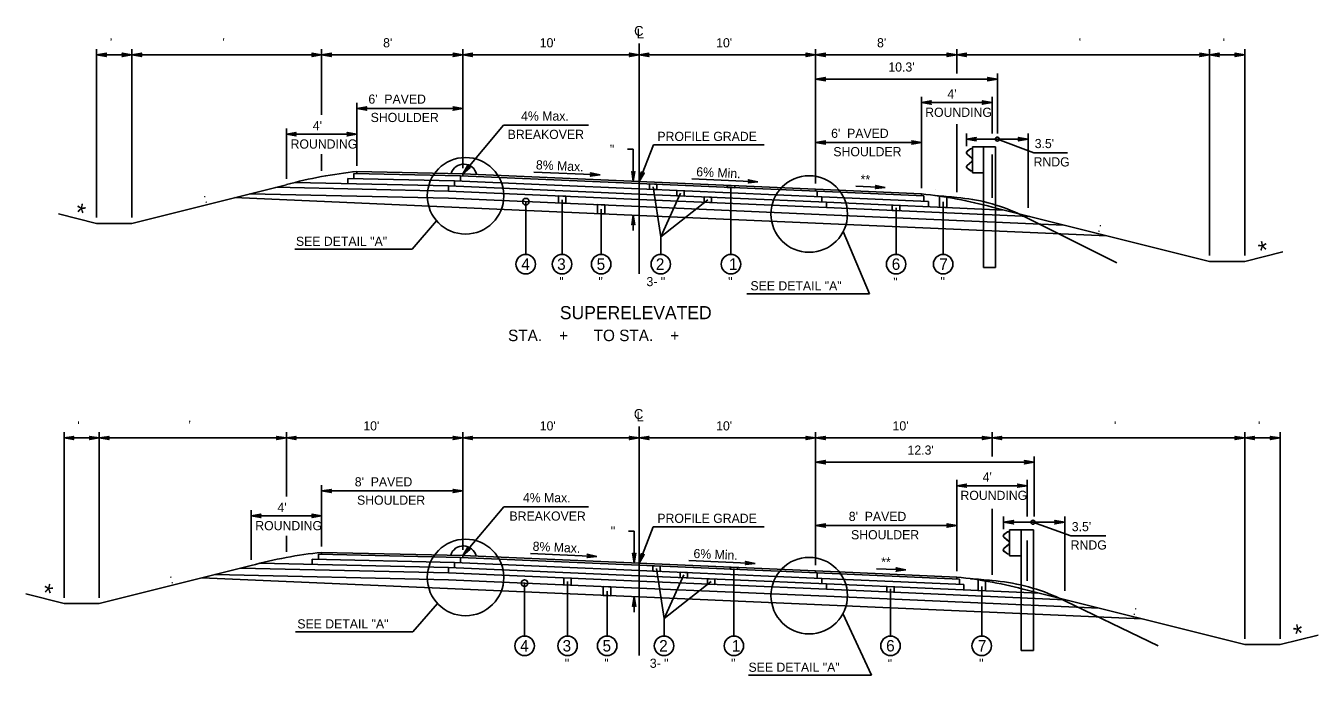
# Model space of a CAD drawing. Extents: x -592 to 1199, y -590 to 416.
# Drawn here: x 451 to 648.3, y -323.9 to -224.8 of the extents above; entities that cross this region are included whole.
import ezdxf

# ---------------------------------------------------------------- set-up
doc = ezdxf.new("R2010")
doc.units = 0
doc.layers.add('1', color=7, linetype='Continuous')
doc.layers.add('Des_ Drain_ Ftrs', color=7, linetype='Continuous')

msp = doc.modelspace()

# ---------------------------------------------------------------- linework, layer by layer
at = {"layer": '1'}
for p, q in [((461.76, -254.1), (461.76, -228.39)), ((467.15, -254.1), (467.15, -228.39)), ((496.12, -238.44), (496.12, -228.39)), ((517.68, -246.54), (517.68, -228.39)), ((544.62, -262.69), (544.62, -227.51)), ((571.56, -248.9), (571.56, -228.39)), ((593.11, -232.09), (593.11, -228.39)), ((631.7, -259.91), (631.7, -228.39)), ((637.09, -259.91), (637.09, -228.39)), ((467.15, -229.27), (461.76, -229.27)), ((496.12, -229.27), (467.15, -229.27)), ((517.68, -229.27), (496.12, -229.27)), ((544.62, -229.27), (517.68, -229.27)), ((544.62, -229.27), (571.56, -229.27)), ((571.56, -229.27), (593.11, -229.27)), ((593.11, -229.27), (631.7, -229.27)), ((631.7, -229.27), (637.09, -229.27)), ((599.31, -241.25), (599.31, -232.09)), ((571.56, -232.97), (599.31, -232.97)), ((501.51, -246.19), (501.51, -236.59)), ((587.72, -249.6), (587.72, -235.67)), ((587.72, -236.55), (598.5, -236.55)), ((598.5, -241.25), (598.5, -235.67)), ((517.68, -237.47), (501.51, -237.47)), ((490.74, -248.2), (490.74, -240.51)), ((517.67, -247.42), (523.89, -240)), ((536.86, -240), (523.89, -240)), ((593.11, -250.2), (593.11, -239.84)), ((501.51, -241.39), (490.74, -241.39)), ((571.56, -242.64), (587.72, -242.64)), ((594.62, -243.2), (594.62, -241.25)), ((594.62, -242.13), (604, -242.13)), ((599.31, -242.13), (604.87, -244.2)), ((604, -252.61), (604, -241.25)), ((496.12, -246.97), (496.12, -244.43)), ((543.72, -243.68), (542.84, -243.68)), ((543.72, -243.68), (543.72, -248.56)), ((544.63, -248.61), (546.79, -243)), ((563.71, -243), (546.79, -243)), ((594.68, -244.42), (595.41, -245.06)), ((595.21, -243.6), (594.7, -243.99)), ((594.7, -244.4), (595.43, -245.03)), ((595.23, -243.63), (594.71, -244.01)), ((595.53, -243.54), (595.21, -243.6)), ((595.53, -243.57), (595.23, -243.63)), ((595.53, -243.31), (595.53, -247.25)), ((595.53, -243.31), (597.21, -243.31)), ((597.21, -243.31), (597.21, -261.71)), ((599.04, -243.31), (597.21, -243.31)), ((598.5, -251.09), (598.5, -244.48)), ((599.04, -243.31), (599.04, -261.71)), ((604.87, -244.2), (610.02, -244.2)), ((595.41, -245.51), (594.68, -246.14)), ((595.43, -245.53), (594.7, -246.16)), ((594.7, -246.57), (595.21, -246.96)), ((594.71, -246.55), (595.23, -246.93)), ((595.5, -245.24), (595.5, -245.32)), ((595.53, -245.24), (595.53, -245.32)), ((500.13, -248.12), (516.41, -248.48)), ((500.13, -248.91), (500.13, -248.12)), ((501.06, -247.36), (517.33, -247.71)), ((501.06, -248.14), (501.06, -247.36)), ((501.51, -247.07), (517.67, -247.42)), ((501.51, -247.07), (501.51, -247.37)), ((544.62, -249.71), (516.41, -248.48)), ((516.41, -249.29), (516.41, -248.48)), ((544.62, -248.9), (517.33, -247.71)), ((517.33, -248.52), (517.33, -247.71)), ((544.62, -248.6), (517.67, -247.42)), ((517.67, -247.42), (517.67, -247.72)), ((528.53, -247.15), (538.65, -247.59)), ((571.56, -249.78), (544.62, -248.6)), ((552.65, -248.19), (562.76, -248.63)), ((595.21, -246.96), (595.53, -247.02)), ((595.23, -246.93), (595.53, -246.99)), ((595.53, -247.25), (597.21, -247.25)), ((490.74, -249.08), (467.15, -254.98)), ((485.17, -250.47), (515.49, -251.14)), ((489.14, -249.48), (515.49, -250.06)), ((492.06, -248.74), (515.49, -249.25)), ((544.62, -250.52), (515.49, -249.25)), ((515.49, -250.06), (515.49, -249.25)), ((544.62, -251.33), (515.49, -250.06)), ((571.8, -250.09), (544.62, -248.9)), ((572.5, -250.93), (544.62, -249.71)), ((573.21, -251.77), (544.62, -250.52)), ((546.74, -249.4), (547.91, -257.02)), ((550.92, -250.38), (547.91, -257.02)), ((558.63, -249.39), (558.63, -259.72)), ((587.72, -250.48), (571.56, -249.78)), ((571.56, -250.08), (571.56, -249.78)), ((588.09, -250.8), (571.8, -250.09)), ((571.8, -250.09), (571.8, -250.9)), ((582.2, -249.5), (577.7, -249.3)), ((587.72, -250.78), (587.72, -250.48)), ((589.92, -249.87), (589.92, -249.87)), ((544.62, -253.76), (482.84, -251.06)), ((544.62, -252.41), (515.49, -251.14)), ((527.29, -251.67), (527.29, -259.72)), ((532.84, -251.38), (532.84, -259.72)), ((573.21, -252.58), (544.62, -251.33)), ((573.21, -253.66), (544.62, -252.41)), ((555.1, -251.39), (547.91, -257.02)), ((588.78, -251.64), (572.5, -250.93)), ((572.5, -250.93), (572.5, -251.74)), ((573.21, -251.77), (573.21, -252.58)), ((600.33, -252.95), (573.21, -251.77)), ((604.25, -253.93), (573.21, -252.58)), ((588.09, -250.8), (588.09, -251.61)), ((588.78, -251.64), (588.78, -252.45)), ((591.04, -251.69), (591.04, -259.72)), ((594.62, -251.26), (594.62, -251.26)), ((598.5, -252.49), (631.7, -260.79)), ((455.94, -253.52), (461.76, -254.98)), ((538.81, -252.8), (538.81, -259.72)), ((543.72, -253.71), (543.72, -256.08)), ((616.02, -256.87), (544.62, -253.76)), ((609.48, -255.24), (573.21, -253.66)), ((583.85, -252.61), (583.85, -259.72)), ((602.5, -253.49), (617.55, -261.02)), ((467.15, -254.98), (461.76, -254.98)), ((509.94, -258.92), (513.68, -254.6)), ((575.76, -256.25), (579.81, -265.72)), ((547.91, -257.02), (547.91, -259.72)), ((492.01, -258.92), (509.94, -258.92)), ((642.91, -259.34), (637.09, -260.79)), ((599.04, -261.71), (597.21, -261.71)), ((631.7, -260.79), (637.09, -260.79)), ((561.03, -265.72), (579.81, -265.72)), ((544.62, -320.94), (544.62, -285.98)), ((456.78, -312.13), (456.78, -286.86)), ((462.17, -287.74), (456.78, -287.74)), ((462.17, -312.13), (462.17, -286.86)), ((490.74, -287.74), (462.17, -287.74)), ((490.74, -296.69), (490.74, -286.86)), ((517.68, -287.74), (490.74, -287.74)), ((517.68, -304.79), (517.68, -286.86)), ((544.62, -287.74), (517.68, -287.74)), ((544.62, -287.74), (571.56, -287.74)), ((571.56, -307.15), (571.56, -286.86)), ((571.56, -287.74), (598.5, -287.74)), ((598.5, -290.56), (598.5, -286.86)), ((598.5, -287.74), (637.09, -287.74)), ((637.09, -318.4), (637.09, -286.86)), ((637.09, -287.74), (642.48, -287.74)), ((642.48, -318.4), (642.48, -286.86)), ((571.56, -291.44), (604.93, -291.44)), ((604.93, -299.72), (604.93, -290.56)), ((496.12, -304.32), (496.12, -294.95)), ((517.68, -295.83), (496.12, -295.83)), ((593.11, -308.09), (593.11, -294.14)), ((593.11, -295.02), (603.89, -295.02)), ((603.89, -299.72), (603.89, -294.14)), ((485.35, -306.33), (485.35, -298.75)), ((496.12, -299.63), (485.35, -299.63)), ((517.67, -305.67), (523.96, -298.26)), ((536.89, -298.26), (523.96, -298.26)), ((598.5, -308.63), (598.5, -298.57)), ((600.23, -301.67), (600.23, -299.72)), ((609.62, -311.08), (609.62, -299.72)), ((543.86, -301.94), (542.98, -301.94)), ((543.86, -301.94), (543.86, -306.82)), ((544.63, -306.86), (546.77, -301.28)), ((563.69, -301.28), (546.77, -301.28)), ((571.56, -301.11), (593.11, -301.11)), ((600.23, -300.6), (609.62, -300.6)), ((601.18, -301.78), (601.18, -305.71)), ((601.18, -301.78), (602.93, -301.78)), ((602.93, -301.78), (602.93, -320.18)), ((604.82, -301.78), (602.93, -301.78)), ((604.75, -300.6), (610.52, -302.67)), ((604.82, -301.78), (604.82, -320.18)), ((490.74, -305.1), (490.74, -302.7)), ((600.3, -302.89), (601.06, -303.52)), ((600.85, -302.07), (600.32, -302.45)), ((600.32, -302.86), (601.08, -303.5)), ((600.87, -302.09), (600.34, -302.48)), ((601.18, -302.01), (600.85, -302.07)), ((601.18, -302.04), (600.87, -302.09)), ((601.15, -303.71), (601.15, -303.79)), ((601.18, -303.71), (601.18, -303.79)), ((603.89, -309.54), (603.89, -303.39)), ((610.52, -302.67), (615.86, -302.67)), ((495.63, -305.49), (517.33, -305.96)), ((495.63, -306.28), (495.63, -305.49)), ((496.12, -305.2), (517.67, -305.67)), ((496.12, -305.2), (496.12, -305.5)), ((544.62, -306.85), (517.67, -305.67)), ((517.67, -305.97), (517.67, -305.67)), ((528.04, -305.37), (538.15, -305.81)), ((601.06, -303.97), (600.3, -304.61)), ((601.08, -304), (600.32, -304.63)), ((600.32, -305.04), (600.85, -305.43)), ((600.34, -305.02), (600.87, -305.4)), ((600.85, -305.43), (601.18, -305.49)), ((600.87, -305.4), (601.18, -305.46)), ((601.18, -305.71), (602.93, -305.71)), ((485.35, -307.21), (462.17, -313.01)), ((483.75, -307.61), (515.49, -308.3)), ((486.67, -306.87), (515.49, -307.5)), ((494.7, -306.25), (516.41, -306.73)), ((494.7, -306.94), (494.7, -306.25)), ((544.62, -308.77), (515.49, -307.5)), ((515.49, -308.3), (515.49, -307.5)), ((544.62, -307.96), (516.41, -306.73)), ((516.41, -307.54), (516.41, -306.73)), ((544.62, -307.15), (517.33, -305.96)), ((517.33, -306.77), (517.33, -305.96)), ((571.56, -308.03), (544.62, -306.85)), ((571.8, -308.34), (544.62, -307.15)), ((547.25, -307.66), (548.41, -315.29)), ((552.21, -306.45), (562.33, -306.89)), ((559.08, -307.64), (559.08, -317.97)), ((585.34, -307.88), (580.85, -307.69)), ((544.62, -312), (477.85, -309.09)), ((479.79, -308.6), (515.49, -309.38)), ((544.62, -309.58), (515.49, -308.3)), ((544.62, -310.66), (515.49, -309.38)), ((533.68, -309.64), (533.68, -317.97)), ((572.5, -309.18), (544.62, -307.96)), ((573.21, -310.02), (544.62, -308.77)), ((573.21, -310.82), (544.62, -309.58)), ((551.43, -308.64), (548.41, -315.29)), ((555.6, -309.66), (548.41, -315.29)), ((593.11, -308.97), (571.56, -308.03)), ((571.56, -308.33), (571.56, -308.03)), ((593.51, -309.28), (571.8, -308.34)), ((571.8, -308.34), (571.8, -309.15)), ((594.2, -310.12), (572.5, -309.18)), ((572.5, -309.18), (572.5, -309.99)), ((593.11, -308.97), (593.11, -309.27)), ((593.51, -309.28), (593.51, -310.09)), ((600.23, -309.73), (600.23, -309.73)), ((450.95, -311.55), (456.78, -313.01)), ((527.12, -309.89), (527.12, -317.97)), ((539.72, -311.11), (539.72, -317.97)), ((573.21, -311.9), (544.62, -310.66)), ((573.21, -310.02), (573.21, -310.82)), ((605.72, -311.44), (573.21, -310.02)), ((609.64, -312.42), (573.21, -310.82)), ((582.99, -310.79), (582.99, -317.97)), ((594.2, -310.12), (594.2, -310.93)), ((596.93, -310.41), (596.93, -317.97)), ((603.89, -310.98), (637.09, -319.28)), ((462.17, -313.01), (456.78, -313.01)), ((510.07, -317.31), (513.81, -312.99)), ((543.86, -311.97), (543.86, -314.34)), ((621.4, -315.36), (544.62, -312)), ((614.87, -313.72), (573.21, -311.9)), ((608.24, -311.96), (623.85, -319.49)), ((548.41, -315.29), (548.41, -317.97)), ((575.74, -314.54), (580.09, -323.94)), ((492.14, -317.31), (510.07, -317.31)), ((637.09, -319.28), (642.48, -319.28)), ((648.3, -317.82), (642.48, -319.28)), ((604.82, -320.18), (602.93, -320.18)), ((561.3, -323.94), (580.09, -323.94))]:
    msp.add_line(p, q, dxfattribs=at)
for points in [[(546.17, -248.97), (547.32, -249.02), (547.32, -249.83), (546.17, -249.78)], [(550.35, -249.96), (551.49, -250.01), (551.49, -250.82), (550.35, -250.77)], [(558.06, -249.19), (559.2, -249.24), (559.2, -249.54), (558.06, -249.49)], [(532.27, -250.79), (533.41, -250.84), (533.41, -251.92), (532.27, -251.87)], [(538.24, -252.13), (539.38, -252.18), (539.38, -253.53), (538.24, -253.48)], [(554.52, -250.95), (555.67, -251), (555.67, -251.81), (554.52, -251.76)], [(583.27, -252.21), (584.42, -252.26), (584.42, -253.07), (583.27, -253.02)], [(590.47, -250.83), (591.62, -251), (591.62, -252.57), (590.47, -252.52)], [(546.68, -307.24), (547.82, -307.29), (547.82, -308.1), (546.68, -308.05)], [(558.5, -307.46), (559.65, -307.51), (559.65, -307.81), (558.5, -307.76)], [(533.11, -309.07), (534.25, -309.12), (534.25, -310.2), (533.11, -310.15)], [(550.85, -308.23), (552, -308.28), (552, -309.09), (550.85, -309.04)], [(555.03, -309.22), (556.17, -309.27), (556.17, -310.08), (555.03, -310.03)], [(596.36, -309.38), (597.5, -309.57), (597.5, -311.08), (596.36, -311.03)], [(539.14, -310.42), (540.29, -310.47), (540.29, -311.81), (539.14, -311.76)], [(582.42, -310.42), (583.57, -310.47), (583.57, -311.28), (582.42, -311.23)]]:
    msp.add_lwpolyline(points, close=True, dxfattribs=at)
for centre, radius in [((599.31, -242.13), 0.3), ((518.1, -250.78), 5.84), ((570.58, -253.56), 5.84), ((527.29, -251.67), 0.5), ((527.29, -261.21), 1.49), ((532.84, -261.21), 1.49), ((538.81, -261.21), 1.49), ((547.91, -261.21), 1.49), ((558.63, -261.21), 1.49), ((583.85, -261.21), 1.49), ((591.04, -261.21), 1.49), ((518.1, -309.03), 5.84), ((570.58, -311.8), 5.84), ((527.12, -309.89), 0.5), ((527.12, -319.46), 1.49), ((533.68, -319.46), 1.49), ((539.72, -319.46), 1.49), ((548.41, -319.46), 1.49), ((559.08, -319.46), 1.49), ((582.99, -319.46), 1.49), ((596.93, -319.46), 1.49)]:
    msp.add_circle(centre, radius, dxfattribs=at)
for centre, radius, start, end in [((594.86, -244.21), 0.278, 126.9799, 229.021), ((594.86, -244.21), 0.249, 126.9799, 229.021), ((517.83, -247.94), 2, 12.248, 163.8639), ((594.86, -246.35), 0.278, 130.979, 233.0201), ((594.86, -246.35), 0.249, 130.979, 233.0201), ((595.25, -245.24), 0.249, 0, 49.0365), ((595.25, -245.32), 0.249, 310.9635, 0), ((595.25, -245.24), 0.278, 0, 49.0365), ((595.25, -245.32), 0.278, 310.9635, 0), ((508.41, -313.9), 67.19, 95.8897, 105.2483), ((580.84, -317.32), 67.19, 74.7602, 84.1188), ((582.29, -351.7), 101.24, 83.8633, 85.6775), ((590.99, -278.33), 27.37, 65.1374, 85.5513), ((503.02, -372.04), 67.19, 95.8911, 105.2497), ((517.75, -306.21), 2, 12.9578, 163.1197), ((586.23, -375.8), 67.19, 74.7602, 84.1188)]:
    msp.add_arc(centre, radius, start, end, dxfattribs=at)
msp.add_ellipse((604.75, -300.6), major_axis=(-0.311, 0), ratio=0.964041, dxfattribs=at)
for centre, major_axis, start_param, end_param in [((600.49, -302.68), (-0.288, 0), 5.35781, 7.138763), ((600.49, -302.68), (-0.258, 0), 5.35781, 7.138763), ((600.89, -303.71), (0.258, 0), 0, 0.855848), ((600.89, -303.79), (0.258, 0), 5.427337, 6.283185), ((600.89, -303.71), (0.288, 0), 0, 0.855848), ((600.89, -303.79), (0.288, 0), 5.427337, 6.283185), ((600.49, -304.82), (-0.288, 0), 5.427608, 7.208561), ((600.49, -304.82), (-0.258, 0), 5.427608, 7.208561), ((587.28, -410.17), (105.02, 0), 1.463691, 1.495354), ((596.3, -336.79), (28.39, 0), 1.136862, 1.493152)]:
    msp.add_ellipse(centre, major_axis=major_axis, ratio=0.964041, start_param=start_param, end_param=end_param, dxfattribs=at)
at = {"layer": 'Des_ Drain_ Ftrs'}
for points in [[(461.76, -229.27), (463.25, -229.52), (462.96, -229.27), (463.25, -229.02)], [(467.15, -229.27), (465.66, -229.52), (465.96, -229.27), (465.66, -229.02)], [(467.15, -229.27), (468.64, -229.52), (468.35, -229.27), (468.64, -229.02)], [(496.12, -229.27), (494.64, -229.52), (494.93, -229.27), (494.64, -229.02)], [(496.12, -229.27), (497.61, -229.52), (497.32, -229.27), (497.61, -229.02)], [(517.68, -229.27), (516.19, -229.52), (516.48, -229.27), (516.19, -229.02)], [(517.68, -229.27), (519.16, -229.52), (518.87, -229.27), (519.16, -229.02)], [(544.62, -229.27), (543.13, -229.52), (543.42, -229.27), (543.13, -229.02)], [(544.62, -229.27), (546.11, -229.52), (545.81, -229.27), (546.11, -229.02)], [(571.56, -229.27), (570.07, -229.52), (570.37, -229.27), (570.07, -229.02)], [(571.56, -229.27), (573.05, -229.52), (572.75, -229.27), (573.05, -229.02)], [(593.11, -229.27), (591.62, -229.52), (591.92, -229.27), (591.62, -229.02)], [(593.11, -229.27), (594.6, -229.52), (594.31, -229.27), (594.6, -229.02)], [(631.7, -229.27), (630.21, -229.52), (630.51, -229.27), (630.21, -229.02)], [(631.7, -229.27), (633.19, -229.52), (632.89, -229.27), (633.19, -229.02)], [(637.09, -229.27), (635.6, -229.52), (635.89, -229.27), (635.6, -229.02)], [(571.56, -232.97), (573.05, -233.22), (572.75, -232.97), (573.05, -232.73)], [(599.31, -232.97), (597.82, -233.22), (598.11, -232.97), (597.82, -232.73)], [(587.72, -236.55), (589.21, -236.8), (588.92, -236.55), (589.21, -236.3)], [(598.5, -236.55), (597.01, -236.8), (597.31, -236.55), (597.01, -236.3)], [(501.51, -237.47), (503, -237.72), (502.71, -237.47), (503, -237.22)], [(517.68, -237.47), (516.19, -237.72), (516.48, -237.47), (516.19, -237.22)], [(490.74, -241.39), (492.22, -241.64), (491.93, -241.39), (492.22, -241.14)], [(501.51, -241.39), (500.02, -241.64), (500.32, -241.39), (500.02, -241.14)], [(571.56, -242.64), (573.05, -242.88), (572.75, -242.64), (573.05, -242.39)], [(587.72, -242.64), (586.24, -242.88), (586.53, -242.64), (586.24, -242.39)], [(594.62, -242.13), (596.1, -242.38), (595.81, -242.13), (596.1, -241.88)], [(604, -242.13), (602.51, -242.38), (602.81, -242.13), (602.51, -241.88)], [(517.67, -247.42), (518.82, -246.44), (518.44, -246.51), (518.44, -246.12)], [(538.65, -247.59), (537.15, -247.77), (537.45, -247.54), (537.17, -247.28)], [(543.72, -248.56), (543.97, -247.07), (543.72, -247.37), (543.47, -247.07)], [(544.63, -248.61), (545.39, -247.31), (545.05, -247.49), (544.93, -247.13)], [(562.76, -248.63), (561.26, -248.81), (561.57, -248.58), (561.28, -248.32)], [(582.2, -249.5), (580.7, -249.68), (581, -249.45), (580.72, -249.19)], [(543.72, -253.71), (543.97, -255.2), (543.72, -254.91), (543.47, -255.2)], [(456.78, -287.74), (458.27, -287.99), (457.97, -287.74), (458.27, -287.49)], [(462.17, -287.74), (460.68, -287.99), (460.97, -287.74), (460.68, -287.49)], [(462.17, -287.74), (463.65, -287.99), (463.36, -287.74), (463.65, -287.49)], [(490.74, -287.74), (489.25, -287.99), (489.54, -287.74), (489.25, -287.49)], [(490.74, -287.74), (492.22, -287.99), (491.93, -287.74), (492.22, -287.49)], [(517.68, -287.74), (516.19, -287.99), (516.48, -287.74), (516.19, -287.49)], [(517.68, -287.74), (519.16, -287.99), (518.87, -287.74), (519.16, -287.49)], [(544.62, -287.74), (543.13, -287.99), (543.42, -287.74), (543.13, -287.49)], [(544.62, -287.74), (546.11, -287.99), (545.81, -287.74), (546.11, -287.49)], [(571.56, -287.74), (570.07, -287.99), (570.37, -287.74), (570.07, -287.49)], [(571.56, -287.74), (573.05, -287.99), (572.75, -287.74), (573.05, -287.49)], [(598.5, -287.74), (597.01, -287.99), (597.31, -287.74), (597.01, -287.49)], [(598.5, -287.74), (599.99, -287.99), (599.69, -287.74), (599.99, -287.49)], [(637.09, -287.74), (635.6, -287.99), (635.89, -287.74), (635.6, -287.49)], [(637.09, -287.74), (638.58, -287.99), (638.28, -287.74), (638.58, -287.49)], [(642.48, -287.74), (640.99, -287.99), (641.28, -287.74), (640.99, -287.49)], [(571.56, -291.44), (573.05, -291.69), (572.75, -291.44), (573.05, -291.19)], [(604.93, -291.44), (603.44, -291.69), (603.73, -291.44), (603.44, -291.19)], [(496.12, -295.83), (497.61, -296.07), (497.32, -295.83), (497.61, -295.58)], [(517.68, -295.83), (516.19, -296.07), (516.48, -295.83), (516.19, -295.58)], [(593.11, -295.02), (594.6, -295.26), (594.31, -295.02), (594.6, -294.77)], [(603.89, -295.02), (602.4, -295.26), (602.69, -295.02), (602.4, -294.77)], [(485.35, -299.63), (486.84, -299.88), (486.54, -299.63), (486.84, -299.39)], [(496.12, -299.63), (494.64, -299.88), (494.93, -299.63), (494.64, -299.39)], [(571.56, -301.11), (573.05, -301.36), (572.75, -301.11), (573.05, -300.86)], [(593.11, -301.11), (591.62, -301.36), (591.92, -301.11), (591.62, -300.86)], [(600.23, -300.6), (601.78, -300.85), (601.47, -300.6), (601.78, -300.35)], [(609.62, -300.6), (608.07, -300.85), (608.38, -300.6), (608.07, -300.35)], [(517.67, -305.67), (518.82, -304.7), (518.44, -304.76), (518.44, -304.38)], [(538.15, -305.81), (536.65, -305.99), (536.96, -305.76), (536.67, -305.49)], [(543.86, -306.82), (544.11, -305.33), (543.86, -305.62), (543.61, -305.33)], [(544.63, -306.86), (545.39, -305.55), (545.05, -305.74), (544.93, -305.38)], [(562.33, -306.89), (560.83, -307.07), (561.13, -306.84), (560.85, -306.58)], [(585.34, -307.88), (583.84, -308.07), (584.15, -307.83), (583.86, -307.57)], [(543.86, -311.97), (544.11, -313.46), (543.86, -313.16), (543.61, -313.46)]]:
    msp.add_lwpolyline(points, close=True, dxfattribs=at)

# ---------------------------------------------------------------- texts
at = {"layer": '1'}
for s, height, p in [(" '", 1.4, (463.26, -228.12)), ("  '", 1.4, (479.94, -228.12)), ("8'", 1.4, (505.51, -228.12)), ("10'", 1.4, (529.43, -228.12)), ("10'", 1.4, (556.37, -228.12)), ("8'", 1.4, (580.94, -228.12)), ("  '", 1.4, (610.71, -228.12)), (" '", 1.4, (633.2, -228.12)), ("10.3'", 1.4, (582.67, -231.82)), ("4'", 1.4, (591.68, -235.93)), ("6'  PAVED", 1.4, (503.26, -236.72)), ('SHOULDER', 1.4, (503.61, -239.52)), ('4% Max.', 1.4, (526.58, -239.3)), ('ROUNDING', 1.4, (588.29, -238.73)), ("4'", 1.4, (494.77, -240.77)), ('BREAKOVER', 1.4, (524.53, -242.1)), ("6'  PAVED", 1.4, (573.93, -241.94)), ('ROUNDING', 1.4, (491.38, -243.57)), ('PROFILE GRADE', 1.4, (547.4, -242.41)), ("3.5'", 1.4, (605.02, -243.5)), ('SHOULDER', 1.4, (574.27, -244.74)), ('RNDG', 1.4, (604.85, -246.3)), ('SEE DETAIL "A"', 1.4, (492.2, -258.42)), ('4', 1.75, (526.61, -262.08)), ('3', 1.75, (532.09, -262.08)), ('5', 1.75, (538.12, -262.08)), ('2', 1.75, (547.16, -262.08)), ('1', 1.75, (558.33, -262.08)), ('6', 1.75, (583.18, -262.08)), ('7', 1.75, (590.45, -262.08)), (' "', 1.4, (531.9, -264.57)), (' "', 1.4, (537.87, -264.57)), ('3- "', 1.4, (545.73, -264.57)), (' "', 1.4, (557.69, -264.57)), ('SEE DETAIL "A"', 1.4, (561.61, -265.21)), (' "', 1.4, (582.9, -264.66)), ('  "', 1.4, (589.6, -264.57)), ('SUPERELEVATED', 2, (532.5, -269.61)), ('STA.    +      TO STA.    +     ', 1.75, (524.59, -272.96)), (" '", 1.4, (458.28, -286.59)), ("  '", 1.4, (474.75, -286.52)), ("10'", 1.4, (502.49, -286.59)), ("10'", 1.4, (529.43, -286.59)), ("10'", 1.4, (556.37, -286.59)), ("10'", 1.4, (583.31, -286.59)), ("  '", 1.4, (616.1, -286.59)), (" '", 1.4, (638.59, -286.59)), ("12.3'", 1.4, (585.6, -290.29)), ("8'  PAVED", 1.4, (501.18, -295.13)), ("4'", 1.4, (597.07, -294.4)), ('ROUNDING', 1.4, (593.68, -297.2)), ("4'", 1.4, (489.38, -299.02)), ('SHOULDER', 1.4, (501.53, -297.93)), ('4% Max.', 1.4, (526.86, -297.56)), ('BREAKOVER', 1.4, (524.81, -300.36)), ('PROFILE GRADE', 1.4, (547.39, -300.7)), ("8'  PAVED", 1.4, (576.62, -300.41)), ('ROUNDING', 1.4, (485.99, -301.82)), ('SHOULDER', 1.4, (576.97, -303.21)), ("3.5'", 1.4, (610.68, -301.97)), ('RNDG', 1.4, (610.51, -304.77)), ('SEE DETAIL "A"', 1.4, (492.41, -316.81)), ('4', 1.75, (526.44, -320.33)), ('3', 1.75, (532.92, -320.33)), ('5', 1.75, (539.02, -320.33)), ('2', 1.75, (547.67, -320.33)), ('1', 1.75, (558.77, -320.33)), ('6', 1.75, (582.33, -320.33)), ('7', 1.75, (596.34, -320.33)), (' "', 1.4, (532.74, -322.82)), (' "', 1.4, (538.77, -322.82)), ('3- "', 1.4, (546.24, -322.82)), (' "', 1.4, (558.13, -322.82)), (' "', 1.4, (582.05, -322.91)), ('  "', 1.4, (595.49, -322.82)), ('SEE DETAIL "A"', 1.4, (561.31, -323.43))]:
    msp.add_text(s, height=height, dxfattribs=at).set_placement(p)
for s, height, rotation, p in [('  "', 1.4, 0.1438, (539.11, -244.39)), ('8% Max.', 1.4, 357.376, (528.82, -246.73)), ('6% Min.', 1.4, 357.3731, (553.31, -247.79)), ('**', 1.4, 357.2163, (578.38, -248.94)), ('*', 2.8, 347.1521, (458.25, -254.55)), (' : ', 1.4, 14.2282, (477.76, -252.04)), (' : ', 1.4, 345.7718, (614.05, -256.09)), ('*', 2.8, 12.8479, (639.55, -260.6)), ('  "', 1.4, 0.1438, (539.25, -302.64)), ('8% Max.', 1.4, 357.3761, (528.32, -304.95)), ('6% Min.', 1.4, 357.373, (552.88, -306.05)), ('**', 1.4, 357.2162, (581.53, -307.32)), (' : ', 1.4, 14.2282, (472.58, -310.12)), ('*', 2.8, 347.1521, (453.26, -312.58)), (' : ', 1.4, 345.7718, (619.44, -314.57)), ('*', 2.8, 12.8479, (644.94, -319.09))]:
    msp.add_text(s, height=height, rotation=rotation, dxfattribs=at).set_placement(p)
at = {"layer": 'Des_ Drain_ Ftrs'}
for s, p in [('C', (543.84, -226.36)), ('L', (544.23, -226.76)), ('C', (543.8, -284.83)), ('L', (544.2, -285.22))]:
    msp.add_text(s, height=1.5, dxfattribs=at).set_placement(p)

doc.saveas('drawing.dxf')
